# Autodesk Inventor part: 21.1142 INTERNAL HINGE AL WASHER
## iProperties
Created: 2007-01
Part Number: 21.1142 INTERNAL HINGE AL WASHER
Document SubType Name: Modeling
Designer: Andy Moles
Material: UHMW, White
Mass: 0.458415 g
Surface Area: 5.70011 cm^2
Volume: 0.487676 cm^3
Density: 0.94 g/cm^3
Author: Andy Moles
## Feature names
1. Extrusion1
